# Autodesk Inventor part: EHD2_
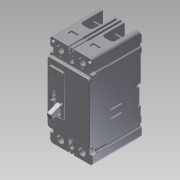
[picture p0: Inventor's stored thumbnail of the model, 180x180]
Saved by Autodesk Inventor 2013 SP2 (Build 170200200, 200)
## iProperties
Created: 2014-08
Part Number: EHD2_
Material: Generic
Document SubType Name: Modeling
Designer: DM/JS
Density: 1 g/cm^3
Description: TYPE EHD THERMAL MAGNETIC CIRCUIT BREAKERS TWO POLE, SERIES C
Translation Standard: STEP AP214IS
FileName: Y:\ECO-062745\WIP\New\FD2_.stp
PreProcessor: Autodesk Inventor 2012
PostProcessor: Build: 219, Release: 2012 SP2 - Date: Fri 04/27/2012
Sent Units: inch
Uncertainty: 0.00039370078740199997
MXEDIT: false
MXINVTNRV: INV Versioned Component|EHD2_|003.0
Author: DM/JS
Revision Number: 003
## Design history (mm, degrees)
node "EHD2_"
node "L1"
node "L2"
node "T1"
node "T2"
body "Solid1"
node "Base1"
